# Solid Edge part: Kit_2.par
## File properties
Sűrűség: 0,000 kg/m^3
Pontosság: 0,990
Author: bmolnar
Last saved by: bmolnar
Revision: 77
Username: bmolnar
Dokumentum tartalom típus: 0
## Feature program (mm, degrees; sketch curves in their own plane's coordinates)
base feature "unnamed BaseFeature 1"
thread "unnamed Thread 1"
thread "unnamed Thread 2"
sketch for "Furat_1" plane through (-18.15, -81.65, 0) normal (1, 0, 0) x-axis (0, 0, 1)
  hole centre (0, -13.85) bore radius 2.067
hole "Furat_1" nominal diameter 5 finite  StartChamferOffset = 0.6 mm; StartChamferAngle = 45 deg
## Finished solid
Body 1: solid body, 263 faces, 638 edges, 388 vertices, 2 internal voids.
  Faces by surface: plane 127, cylinder 56, swept 43, cone 31, torus 6
  Edges by curve: line 385, circle 153, spline 90, curve on surface 5, intersection 4, ellipse 1
Bounding box of the edges (mm; curved faces can reach further): 36.300 x 11.800 x 36.300, from (-18.15, -75.3, -18.15) to (18.15, -63.5, 18.15).
Cylindrical faces by radius (mm): R0.2 x18, R0.4307 x1, R0.4865 x1, R2.067 x3, R2.5 x2, R3.5 x4, R3.75 x2, R4 x4, R4.1 x12, R5.24 x1, R5.45 x2, R5.55 x2, R5.7 x1, R6 x1, R11.25 x2
Conical faces (half-angle, radius in mm at the cone's reference point): 0.5 deg R4.5 x4, 14 deg R5.12 x1, 14 deg R5.3801 x1, 15 deg R2.567 x4, 15 deg R3.433 x4, 17 deg R5.12 x1, 23 deg R5.7369 x1, 42.5 deg R5.1096 x1, 45 deg R2.317 x2, 45 deg R2.667 x1, 45 deg R3.55 x2, 45 deg R4.25 x2, 45 deg R5.3 x2, 45 deg R5.35 x2, 45 deg R5.85 x1, 84 deg R5.4096 x1, 87 deg R5.1371 x1
Toroidal faces (ring radius, tube radius in mm): R3.8 r0.2 x2, R4.4 r0.4 x2, R5.6606 r0.18 x1, R6.1131 r0.26 x1
Planar faces by outward normal: +x 5, +y 5, +z 17, -x 7, -y 14, -z 15, oblique 64
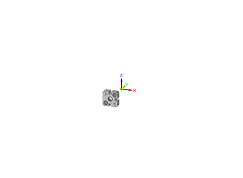
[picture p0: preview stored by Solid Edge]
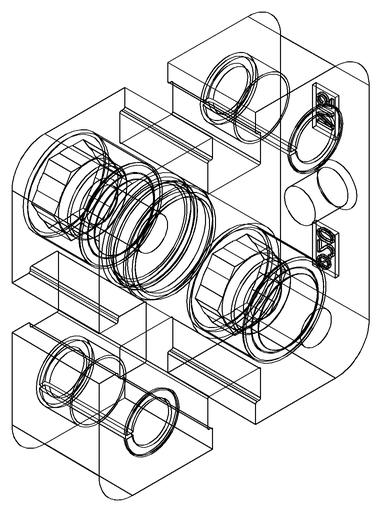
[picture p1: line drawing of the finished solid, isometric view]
